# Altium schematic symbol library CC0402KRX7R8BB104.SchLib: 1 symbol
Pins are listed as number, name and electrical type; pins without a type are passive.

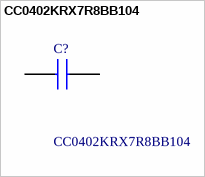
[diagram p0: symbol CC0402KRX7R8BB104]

## CC0402KRX7R8BB104
designator C?
0.1 F +/-10% 25V Ceramic Capacitor X7R 0402 (1005 Metric); Manufacturer_Name: YAGEO; Geometry.Height: 0.55mm
footprint CAPC1005X55N
pins: 1, 2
